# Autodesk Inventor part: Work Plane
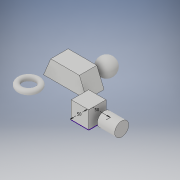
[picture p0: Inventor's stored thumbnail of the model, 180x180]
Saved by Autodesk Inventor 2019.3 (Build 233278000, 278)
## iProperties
Created: 2018-06
Part Number: Work Plane
Material: Generic
Document SubType Name: Modeling
Designer: Power User
Density: 1 g/cm^3
Appearance: Default
Author: Power User
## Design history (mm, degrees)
sketch "Sketch1"
  geometry: L1 (0, 0)-(50, 0); L2 (50, 0)-(50, -50); L3 (50, -50)-(0, -50); L4 (0, -50)-(0, 0)
  constraints: 8 end point, 2 parallel, 1 horizontal, 1 perpendicular
  dimensions: "d0" = 50 distance of L1.end L2.end; "d1" = 50 distance of L2.end L3.end
extrude "Extrusion1" new body sketch "Sketch1" distance "d2" = 50; taper "d3" = 0 deg
workplane "Work Plane1"
sketch "Sketch2"
  geometry: L1 (0, 50)-(50, 50) reference; L2 (50, 0)-(50, 50) reference; C1 r 20 at (25, 25); 3 further points
  constraints: 2 midpoint, 1 centre point, 1 horizontal alignment, 1 vertical alignment
  dimensions: "d5" = 40 diameter of C1
extrude "Extrusion2" new body sketch "Sketch2" distance "d6" = 50; taper "d7" = 0 deg
sketch "Sketch3"
  geometry: L1 (-172.16, 49.98)-(-172.16, 11.482); C1 r 7.5 at (-197.16, 26.587); 1 further point
  constraints: 2 end point, 1 centre point, 1 vertical
  dimensions: "d8" = 15 diameter of C1; "d9" = 50 diameter of C1.centre L1
revolve "Revolution1" sketch "Sketch3" stored, may be unused: angle "d10" = 90 deg
workplane "Work Plane2"
sketch "Sketch4"
  geometry: L1 (-98.807, 58.325)-(-98.807, 8.325); A1 r 25 centre (-98.807, 33.325) between (-98.807, 58.325) and (-98.807, 8.325); 1 further point
  constraints: 2 end point, 2 point on circle, 1 centre point, 1 vertical
  dimensions: "d12" = 50 diameter of A1
revolve "Revolution2" sketch "Sketch4" stored, may be unused: angle "d13" = 90 deg
workplane "Work Plane3"
sketch "Sketch5"
  geometry: L1 (-192.037, 9.98)-(-171.326, 59.98); L2 (-171.326, 59.98)-(-89.041, 59.98); L3 (-89.041, 59.98)-(-68.33, 9.98); L4 (-68.33, 9.98)-(-192.037, 9.98); L5 (-130.184, 59.98)-(-130.184, 9.98); 1 further point
  constraints: 10 end point, 2 midpoint, 1 horizontal, 1 parallel, 1 perpendicular, 1 other
  dimensions: "d15" = 50 distance between parallel lines of L4 L2; "d16" = 45 deg angle of L3 L1
extrude "Extrusion3" new body sketch "Sketch5" stored distance "d17" = 50; taper "d18" = 0 deg
body "Solid1"
body "Solid2"
body "Solid3"
body "Solid4"
body "Solid5"
other parameters: "d14" = -87.5
